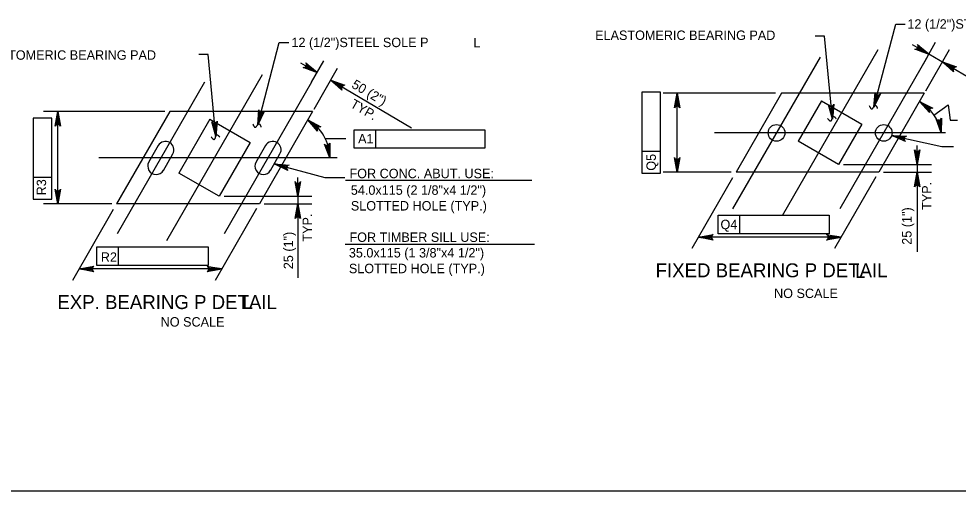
# Model space of a CAD drawing. Extents: x 638175 to 640495, y 294277 to 298435.
# Drawn here: x 639510.9 to 639809.5, y 297856.5 to 298006.7 of the extents above; entities that cross this region are included whole.
import ezdxf

# ---------------------------------------------------------------- set-up
doc = ezdxf.new("R2010")
doc.units = 0
for name, color, linetype in [('2', 7, 'Continuous'), ('3', 7, 'Continuous'), ('4', 7, 'Continuous')]:
    doc.layers.add(name, color=color, linetype=linetype)

# ---------------------------------------------------------------- blocks, each defined once
blk = doc.blocks.new('25S')
at = {"layer": '4'}
blk.add_open_spline([(-1.68325, 0.611625), (-0.867125, -1.69875), (0.901125, 1.69875), (1.58125, -0.611625)], degree=2, dxfattribs=at)

msp = doc.modelspace()

# ---------------------------------------------------------------- linework, layer by layer
at = {"layer": '2'}
msp.add_line((640102.46, 297856.46), (639316.46, 297856.46), dxfattribs=at)
at = {"layer": '3'}
for p, q in [((639765.58, 297994.53), (639737.8, 297946.31)), ((639783.96, 297996.82), (639753.56, 297944.02)), ((639799.65, 297994.53), (639771.88, 297946.31)), ((639588.31, 297988.85), (639557.91, 297936.05)), ((639569.92, 297986.56), (639542.15, 297938.33)), ((639604, 297986.56), (639576.22, 297938.33)), ((639753.36, 297983.06), (639738.89, 297957.93)), ((639798.72, 297983.06), (639753.36, 297983.06)), ((639798.72, 297983.06), (639784.25, 297957.93)), ((639766.07, 297980.6), (639758.68, 297967.76)), ((639766.07, 297980.6), (639778.86, 297973.23)), ((639558.94, 297977.22), (639542.01, 297947.83)), ((639604.29, 297977.22), (639558.94, 297977.22)), ((639604.29, 297977.22), (639587.37, 297947.83)), ((639571.64, 297974.76), (639561.8, 297957.66)), ((639571.64, 297974.76), (639584.44, 297967.39)), ((639778.86, 297973.23), (639771.47, 297960.39)), ((639584.44, 297967.39), (639574.59, 297950.29)), ((639771.47, 297960.39), (639758.68, 297967.76)), ((639555.24, 297966.38), (639552.25, 297961.18)), ((639589.32, 297966.38), (639586.32, 297961.18)), ((639556.86, 297958.52), (639559.85, 297963.73)), ((639590.93, 297958.52), (639593.92, 297963.73)), ((639574.59, 297950.29), (639561.8, 297957.66)), ((639784.25, 297957.93), (639738.89, 297957.93)), ((639587.37, 297947.83), (639542.01, 297947.83))]:
    msp.add_line(p, q, dxfattribs=at)
for centre in [(639751.76, 297970.42), (639785.83, 297970.42)]:
    msp.add_circle(centre, 2.66, dxfattribs=at)
for centre, start, end in [((639557.55, 297965.05), 330.0642, 150.0642), ((639591.62, 297965.05), 330.0642, 150.0642), ((639554.55, 297959.85), 150.0642, 330.0642), ((639588.62, 297959.85), 150.0642, 330.0642)]:
    msp.add_arc(centre, 2.66, start, end, dxfattribs=at)
at = {"layer": '4'}
for p, q in [((639782.73, 297978.58), (639789.66, 298004.97)), ((639789.66, 298004.97), (639792.66, 298004.97)), ((639767.04, 298001.23), (639764.04, 298001.23)), ((639769.56, 297974.83), (639767.04, 298001.23)), ((639586.86, 297972.99), (639593.72, 297999.13)), ((639593.72, 297999.13), (639596.72, 297999.13)), ((639800.16, 297995.46), (639794.98, 297998.45)), ((639798.42, 297992.41), (639802.31, 297999.24)), ((639571.1, 297995.39), (639568.1, 297995.39)), ((639573.58, 297969.38), (639571.1, 297995.39)), ((639799.23, 297983.78), (639806.69, 297996.9)), ((639800.2, 297995.53), (639826.07, 297980.3)), ((639605.73, 297989.62), (639600.55, 297992.6)), ((639604, 297986.56), (639607.88, 297993.39)), ((639604.81, 297977.93), (639612.26, 297991.05)), ((639610.05, 297987.17), (639635.68, 297972.09)), ((639714.84, 297983.35), (639708.93, 297983.35)), ((639708.93, 297983.35), (639708.93, 297957.61)), ((639714.84, 297957.61), (639714.84, 297983.35)), ((639751.42, 297983.06), (639715.69, 297983.06)), ((639720.19, 297957.93), (639720.19, 297983.06)), ((639801.78, 297976.06), (639806.31, 297979.4)), ((639806.31, 297979.4), (639806.9, 297974.44)), ((639557.37, 297977.22), (639518.81, 297977.22)), ((639523.31, 297947.83), (639523.31, 297977.22)), ((639515.48, 297975.06), (639515.48, 297949.31)), ((639521.39, 297975.06), (639515.48, 297975.06)), ((639521.39, 297949.31), (639521.39, 297975.06)), ((639806.9, 297974.44), (639809.27, 297974.44)), ((639617.53, 297971.36), (639659.06, 297971.36)), ((639617.53, 297965.59), (639617.53, 297971.36)), ((639624.42, 297965.59), (639624.42, 297971.36)), ((639659.06, 297971.36), (639659.06, 297965.59)), ((639805.51, 297970.42), (639732.02, 297970.42)), ((639608.36, 297968.6), (639614.84, 297968.6)), ((639788.36, 297969.59), (639804.31, 297966.07)), ((639659.06, 297965.59), (639617.53, 297965.59)), ((639714.84, 297964.49), (639708.93, 297964.49)), ((639796.47, 297963.39), (639796.47, 297966.39)), ((639804.31, 297966.07), (639808.01, 297966.07)), ((639612.12, 297962.45), (639536.36, 297962.45)), ((639592.12, 297960.58), (639608.14, 297956.22)), ((639773.03, 297960.39), (639800.97, 297960.39)), ((639796.47, 297960.39), (639796.47, 297932.63)), ((639521.39, 297956.2), (639515.48, 297956.2)), ((639599.59, 297950.29), (639599.59, 297956.29)), ((639608.14, 297956.22), (639614.51, 297956.22)), ((639614.75, 297955.39), (639673.95, 297955.39)), ((639708.93, 297957.61), (639714.84, 297957.61)), ((639737.33, 297957.93), (639715.69, 297957.93)), ((639724.95, 297933.73), (639737.91, 297956.22)), ((639770.31, 297933.73), (639783.46, 297956.56)), ((639785.81, 297957.93), (639800.97, 297957.93)), ((639515.48, 297949.31), (639521.39, 297949.31)), ((639576.15, 297950.29), (639604.09, 297950.29)), ((639599.59, 297950.29), (639599.59, 297924.29)), ((639540.45, 297947.83), (639518.81, 297947.83)), ((639573.43, 297923.63), (639586.58, 297946.46)), ((639588.93, 297947.83), (639604.09, 297947.83)), ((639528.07, 297923.63), (639541.03, 297946.13)), ((639733.18, 297944.27), (639768.48, 297944.27)), ((639733.18, 297938.37), (639733.18, 297944.27)), ((639740.07, 297938.37), (639740.07, 297944.27)), ((639768.48, 297944.27), (639768.48, 297938.37)), ((639768.48, 297938.37), (639733.18, 297938.37)), ((639614.64, 297935.06), (639674.8, 297935.06)), ((639772.33, 297937.23), (639726.97, 297937.23)), ((639535.75, 297934.17), (639571.05, 297934.17)), ((639535.75, 297928.27), (639535.75, 297934.17)), ((639542.64, 297928.27), (639542.64, 297934.17)), ((639571.05, 297934.17), (639571.05, 297928.27)), ((639575.45, 297927.14), (639530.09, 297927.14)), ((639571.05, 297928.27), (639535.75, 297928.27))]:
    msp.add_line(p, q, dxfattribs=at)
for points in [[(639800.16, 297995.46), (639795.68, 297997.03), (639796.12, 297997.07), (639796.44, 297997.24), (639796.64, 297997.49), (639796.75, 297997.79), (639796.75, 297998.15), (639796.56, 297998.54), (639800.16, 297995.46), (639796.75, 297998.15), (639796.75, 297997.79), (639800.16, 297995.46), (639796.64, 297997.49), (639796.44, 297997.24), (639800.16, 297995.46), (639796.12, 297997.07)], [(639605.73, 297989.62), (639601.26, 297991.19), (639601.69, 297991.22), (639602.01, 297991.4), (639602.21, 297991.65), (639602.32, 297991.94), (639602.32, 297992.31), (639602.13, 297992.7), (639605.73, 297989.62), (639602.32, 297992.31), (639602.32, 297991.94), (639605.73, 297989.62), (639602.21, 297991.65), (639602.01, 297991.4), (639605.73, 297989.62), (639601.69, 297991.22)], [(639804.48, 297993.01), (639808.94, 297991.4), (639808.5, 297991.37), (639808.18, 297991.19), (639807.98, 297990.95), (639807.87, 297990.65), (639807.87, 297990.29), (639808.05, 297989.89), (639804.48, 297993.01), (639807.87, 297990.29), (639807.87, 297990.65), (639804.48, 297993.01), (639807.98, 297990.95), (639808.18, 297991.19), (639804.48, 297993.01), (639808.5, 297991.37)], [(639610.05, 297987.17), (639614.51, 297985.56), (639614.08, 297985.52), (639613.76, 297985.35), (639613.56, 297985.11), (639613.44, 297984.81), (639613.44, 297984.45), (639613.63, 297984.05), (639610.05, 297987.17), (639613.44, 297984.45), (639613.44, 297984.81), (639610.05, 297987.17), (639613.56, 297985.11), (639613.76, 297985.35), (639610.05, 297987.17), (639614.08, 297985.52)], [(639720.19, 297983.06), (639721.06, 297978.4), (639720.81, 297978.76), (639720.5, 297978.94), (639720.19, 297979), (639719.88, 297978.94), (639719.56, 297978.76), (639719.32, 297978.4), (639720.19, 297983.06), (639719.56, 297978.76), (639719.88, 297978.94), (639720.19, 297983.06), (639720.19, 297979), (639720.5, 297978.94), (639720.19, 297983.06), (639720.81, 297978.76)], [(639782.73, 297978.58), (639783.07, 297983.31), (639783.22, 297982.9), (639783.48, 297982.64), (639783.77, 297982.51), (639784.08, 297982.48), (639784.43, 297982.58), (639784.76, 297982.86), (639782.73, 297978.58), (639784.43, 297982.58), (639784.08, 297982.48), (639782.73, 297978.58), (639783.77, 297982.51), (639783.48, 297982.64), (639782.73, 297978.58), (639783.22, 297982.9)], [(639769.56, 297974.83), (639768.25, 297979.38), (639768.53, 297979.05), (639768.86, 297978.89), (639769.17, 297978.87), (639769.48, 297978.95), (639769.77, 297979.17), (639769.99, 297979.55), (639769.56, 297974.83), (639769.77, 297979.17), (639769.48, 297978.95), (639769.56, 297974.83), (639769.17, 297978.87), (639768.86, 297978.89), (639769.56, 297974.83), (639768.53, 297979.05)], [(639797.21, 297980.42), (639801.43, 297978.26), (639800.99, 297978.28), (639800.66, 297978.14), (639800.42, 297977.93), (639800.27, 297977.65), (639800.23, 297977.29), (639800.36, 297976.87), (639797.21, 297980.42), (639800.23, 297977.29), (639800.27, 297977.65), (639797.21, 297980.42), (639800.42, 297977.93), (639800.66, 297978.14), (639797.21, 297980.42), (639800.99, 297978.28)], [(639523.31, 297977.22), (639524.18, 297972.56), (639523.93, 297972.92), (639523.62, 297973.1), (639523.31, 297973.16), (639523, 297973.1), (639522.68, 297972.92), (639522.44, 297972.56), (639523.31, 297977.22), (639522.68, 297972.92), (639523, 297973.1), (639523.31, 297977.22), (639523.31, 297973.16), (639523.62, 297973.1), (639523.31, 297977.22), (639523.93, 297972.92)], [(639586.86, 297972.99), (639587.2, 297977.72), (639587.35, 297977.31), (639587.6, 297977.06), (639587.89, 297976.92), (639588.21, 297976.9), (639588.56, 297977), (639588.89, 297977.28), (639586.86, 297972.99), (639588.56, 297977), (639588.21, 297976.9), (639586.86, 297972.99), (639587.89, 297976.92), (639587.6, 297977.06), (639586.86, 297972.99), (639587.35, 297977.31)], [(639573.58, 297969.38), (639572.27, 297973.94), (639572.55, 297973.61), (639572.88, 297973.45), (639573.19, 297973.43), (639573.5, 297973.51), (639573.79, 297973.72), (639574.01, 297974.11), (639573.58, 297969.38), (639573.79, 297973.72), (639573.5, 297973.51), (639573.58, 297969.38), (639573.19, 297973.43), (639572.88, 297973.45), (639573.58, 297969.38), (639572.55, 297973.61)], [(639602.78, 297974.57), (639606.96, 297972.33), (639606.53, 297972.37), (639606.19, 297972.24), (639605.95, 297972.03), (639605.8, 297971.75), (639605.74, 297971.39), (639605.87, 297970.97), (639602.78, 297974.57), (639605.74, 297971.39), (639605.8, 297971.75), (639602.78, 297974.57), (639605.95, 297972.03), (639606.19, 297972.24), (639602.78, 297974.57), (639606.53, 297972.37)], [(639804.05, 297970.42), (639802.48, 297974.89), (639802.78, 297974.57), (639803.12, 297974.44), (639803.43, 297974.43), (639803.73, 297974.53), (639804.02, 297974.76), (639804.21, 297975.16), (639804.05, 297970.42), (639804.02, 297974.76), (639803.73, 297974.53), (639804.05, 297970.42), (639803.43, 297974.43), (639803.12, 297974.44), (639804.05, 297970.42), (639802.78, 297974.57)], [(639609.78, 297962.46), (639608.05, 297966.87), (639608.36, 297966.57), (639608.7, 297966.44), (639609.02, 297966.45), (639609.32, 297966.56), (639609.59, 297966.8), (639609.76, 297967.2), (639609.78, 297962.46), (639609.59, 297966.8), (639609.32, 297966.56), (639609.78, 297962.46), (639609.02, 297966.45), (639608.7, 297966.44), (639609.78, 297962.46), (639608.36, 297966.57)], [(639788.36, 297969.59), (639793.1, 297969.44), (639792.7, 297969.27), (639792.45, 297969.01), (639792.33, 297968.71), (639792.31, 297968.4), (639792.43, 297968.05), (639792.72, 297967.73), (639788.36, 297969.59), (639792.43, 297968.05), (639792.31, 297968.4), (639788.36, 297969.59), (639792.33, 297968.71), (639792.45, 297969.01), (639788.36, 297969.59), (639792.7, 297969.27)], [(639796.47, 297960.39), (639795.6, 297965.05), (639795.84, 297964.69), (639796.16, 297964.51), (639796.47, 297964.46), (639796.78, 297964.51), (639797.09, 297964.69), (639797.34, 297965.05), (639796.47, 297960.39), (639797.09, 297964.69), (639796.78, 297964.51), (639796.47, 297960.39), (639796.47, 297964.46), (639796.16, 297964.51), (639796.47, 297960.39), (639795.84, 297964.69)], [(639720.19, 297957.93), (639719.32, 297962.59), (639719.56, 297962.23), (639719.88, 297962.05), (639720.19, 297961.99), (639720.5, 297962.05), (639720.81, 297962.23), (639721.06, 297962.59), (639720.19, 297957.93), (639720.81, 297962.23), (639720.5, 297962.05), (639720.19, 297957.93), (639720.19, 297961.99), (639719.88, 297962.05), (639720.19, 297957.93), (639719.56, 297962.23)], [(639592.12, 297960.58), (639596.84, 297960.2), (639596.43, 297960.06), (639596.17, 297959.8), (639596.03, 297959.52), (639596.01, 297959.2), (639596.1, 297958.85), (639596.38, 297958.52), (639592.12, 297960.58), (639596.1, 297958.85), (639596.01, 297959.2), (639592.12, 297960.58), (639596.03, 297959.52), (639596.17, 297959.8), (639592.12, 297960.58), (639596.43, 297960.06)], [(639796.47, 297957.93), (639797.34, 297953.27), (639797.09, 297953.63), (639796.78, 297953.81), (639796.47, 297953.87), (639796.16, 297953.81), (639795.84, 297953.63), (639795.6, 297953.27), (639796.47, 297957.93), (639795.84, 297953.63), (639796.16, 297953.81), (639796.47, 297957.93), (639796.47, 297953.87), (639796.78, 297953.81), (639796.47, 297957.93), (639797.09, 297953.63)], [(639523.31, 297947.83), (639522.44, 297952.49), (639522.68, 297952.13), (639523, 297951.95), (639523.31, 297951.89), (639523.62, 297951.95), (639523.93, 297952.13), (639524.18, 297952.49), (639523.31, 297947.83), (639523.93, 297952.13), (639523.62, 297951.95), (639523.31, 297947.83), (639523.31, 297951.89), (639523, 297951.95), (639523.31, 297947.83), (639522.68, 297952.13)], [(639599.59, 297950.26), (639598.72, 297954.92), (639598.96, 297954.56), (639599.28, 297954.38), (639599.59, 297954.32), (639599.9, 297954.38), (639600.21, 297954.56), (639600.46, 297954.92), (639599.59, 297950.26), (639600.21, 297954.56), (639599.9, 297954.38), (639599.59, 297950.26), (639599.59, 297954.32), (639599.28, 297954.38), (639599.59, 297950.26), (639598.96, 297954.56)], [(639599.59, 297947.83), (639600.46, 297943.17), (639600.21, 297943.53), (639599.9, 297943.72), (639599.59, 297943.77), (639599.28, 297943.72), (639598.96, 297943.53), (639598.72, 297943.17), (639599.59, 297947.83), (639598.96, 297943.53), (639599.28, 297943.72), (639599.59, 297947.83), (639599.59, 297943.77), (639599.9, 297943.72), (639599.59, 297947.83), (639600.21, 297943.53)], [(639726.97, 297937.23), (639731.63, 297938.11), (639731.28, 297937.86), (639731.09, 297937.55), (639731.04, 297937.23), (639731.09, 297936.92), (639731.28, 297936.61), (639731.63, 297936.36), (639726.97, 297937.23), (639731.28, 297936.61), (639731.09, 297936.92), (639726.97, 297937.23), (639731.04, 297937.23), (639731.09, 297937.55), (639726.97, 297937.23), (639731.28, 297937.86)], [(639772.33, 297937.23), (639767.67, 297936.36), (639768.03, 297936.61), (639768.22, 297936.92), (639768.27, 297937.23), (639768.22, 297937.55), (639768.03, 297937.86), (639767.67, 297938.11), (639772.33, 297937.23), (639768.03, 297937.86), (639768.22, 297937.55), (639772.33, 297937.23), (639768.27, 297937.23), (639768.22, 297936.92), (639772.33, 297937.23), (639768.03, 297936.61)], [(639530.09, 297927.14), (639534.76, 297928.01), (639534.4, 297927.76), (639534.21, 297927.45), (639534.16, 297927.14), (639534.21, 297926.82), (639534.4, 297926.51), (639534.76, 297926.26), (639530.09, 297927.14), (639534.4, 297926.51), (639534.21, 297926.82), (639530.09, 297927.14), (639534.16, 297927.14), (639534.21, 297927.45), (639530.09, 297927.14), (639534.4, 297927.76)], [(639575.45, 297927.14), (639570.79, 297926.26), (639571.15, 297926.51), (639571.34, 297926.82), (639571.39, 297927.14), (639571.34, 297927.45), (639571.15, 297927.76), (639570.79, 297928.01), (639575.45, 297927.14), (639571.15, 297927.76), (639571.34, 297927.45), (639575.45, 297927.14), (639571.39, 297927.14), (639571.34, 297926.82), (639575.45, 297927.14), (639571.15, 297926.51)]]:
    msp.add_lwpolyline(points, dxfattribs=at)
for points in [[(639797.83, 297997.38), (639797.33, 297996.52), (639800.18, 297995.45)], [(639603.4, 297991.54), (639602.9, 297990.67), (639605.75, 297989.61)], [(639807.29, 297991.93), (639806.79, 297991.07), (639804.44, 297993)], [(639612.86, 297986.09), (639612.37, 297985.22), (639610.02, 297987.15)], [(639720.69, 297980.06), (639719.69, 297980.06), (639720.19, 297983.06)], [(639784.01, 297981.46), (639783.04, 297981.71), (639782.76, 297978.69)], [(639523.81, 297974.22), (639522.81, 297974.22), (639523.31, 297977.22)], [(639769.75, 297978.12), (639768.76, 297978.02), (639769.54, 297975.08)], [(639588.07, 297975.62), (639587.1, 297975.87), (639586.82, 297972.84)], [(639573.81, 297972.27), (639572.81, 297972.18), (639573.59, 297969.24)], [(639791.39, 297969.43), (639791.17, 297968.46), (639788.35, 297969.59)], [(639796.97, 297963.39), (639795.97, 297963.39), (639796.47, 297960.39)], [(639595.39, 297960.21), (639595.13, 297959.24), (639592.37, 297960.52)], [(639720.69, 297960.93), (639719.69, 297960.93), (639720.19, 297957.93)], [(639796.97, 297954.93), (639795.97, 297954.93), (639796.47, 297957.93)], [(639600.09, 297953.29), (639599.09, 297953.29), (639599.59, 297950.29)], [(639523.81, 297950.83), (639522.81, 297950.83), (639523.31, 297947.83)], [(639600.09, 297944.83), (639599.09, 297944.83), (639599.59, 297947.83)], [(639729.97, 297937.73), (639729.97, 297936.73), (639726.97, 297937.23)], [(639769.33, 297937.73), (639769.33, 297936.73), (639772.33, 297937.23)], [(639533.09, 297927.64), (639533.09, 297926.64), (639530.09, 297927.14)], [(639572.45, 297927.64), (639572.45, 297926.64), (639575.45, 297927.14)]]:
    msp.add_lwpolyline(points, close=True, dxfattribs=at)
for centre, start in [((639790.22, 297968.29), 8.7402), ((639595.79, 297962.45), 359.9962)]:
    msp.add_arc(centre, 14, start, 60.0642, dxfattribs=at)

# ---------------------------------------------------------------- block references
at = {"layer": '4', "xscale": 0.7874015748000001, "yscale": 0.7874015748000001}
for p in [(639782.58, 297978.62), (639586.64, 297972.77)]:
    msp.add_blockref('25S', p, dxfattribs=at)
at = {"layer": '4', "xscale": 0.7874015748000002, "yscale": 0.7874015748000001, "rotation": 19.234247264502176}
for p in [(639769.39, 297974.96), (639573.44, 297969.11)]:
    msp.add_blockref('25S', p, dxfattribs=at)

# ---------------------------------------------------------------- texts
at = {"layer": '4'}
for s, height, p in [('12 (1/2")STEEL SOLE P', 3, (639793.36, 298003.57)), ('ELASTOMERIC BEARING PAD', 3, (639694.1, 297999.99)), ('12 (1/2")STEEL SOLE P', 3, (639597.57, 297997.71)), ('L', 3, (639655.42, 297997.59)), ('ELASTOMERIC BEARING PAD', 3, (639497.25, 297993.69)), ('A1', 3, (639618.76, 297967.08)), ('FOR CONC. ABUT. USE:', 3, (639616.02, 297956.02)), ('54.0x115 (2 1/8"x4 1/2")', 3, (639616.45, 297950.74)), ('SLOTTED HOLE (TYP.)', 3, (639616.45, 297945.74)), ('Q4', 3, (639733.95, 297939.8)), ('FOR TIMBER SILL USE:', 3, (639616.02, 297935.76)), ('R2', 3, (639536.98, 297929.43)), ('35.0x115 (1 3/8"x4 1/2")', 3, (639615.82, 297930.8)), ('SLOTTED HOLE (TYP.)', 3, (639615.82, 297925.8)), ('FIXED BEARING P DETAIL', 4.4292, (639713.32, 297924.5)), ('L', 4.43, (639776.72, 297924.31)), ('NO SCALE', 3, (639750.98, 297917.9)), ('EXP. BEARING P DETAIL', 4.4292, (639523.17, 297914.4)), ('L', 4.43, (639582, 297914.42)), ('NO SCALE', 3, (639556, 297908.82))]:
    msp.add_text(s, height=height, dxfattribs=at).set_placement(p)
for s, rotation, p in [('50 (2")', 329.53, (639616.44, 297984.99)), ('TYP.', 330.0642, (639616.01, 297978.77)), ('Q5', 90, (639713.41, 297958.4)), ('R3', 90, (639519.59, 297950.56)), ('TYP.', 90, (639800.99, 297945.94)), ('25 (1")', 90, (639794.67, 297934.85)), ('TYP.', 90, (639604.11, 297935.84)), ('25 (1")', 90, (639598.1, 297927.08))]:
    msp.add_text(s, height=3, rotation=rotation, dxfattribs=at).set_placement(p)

doc.saveas('drawing.dxf')
